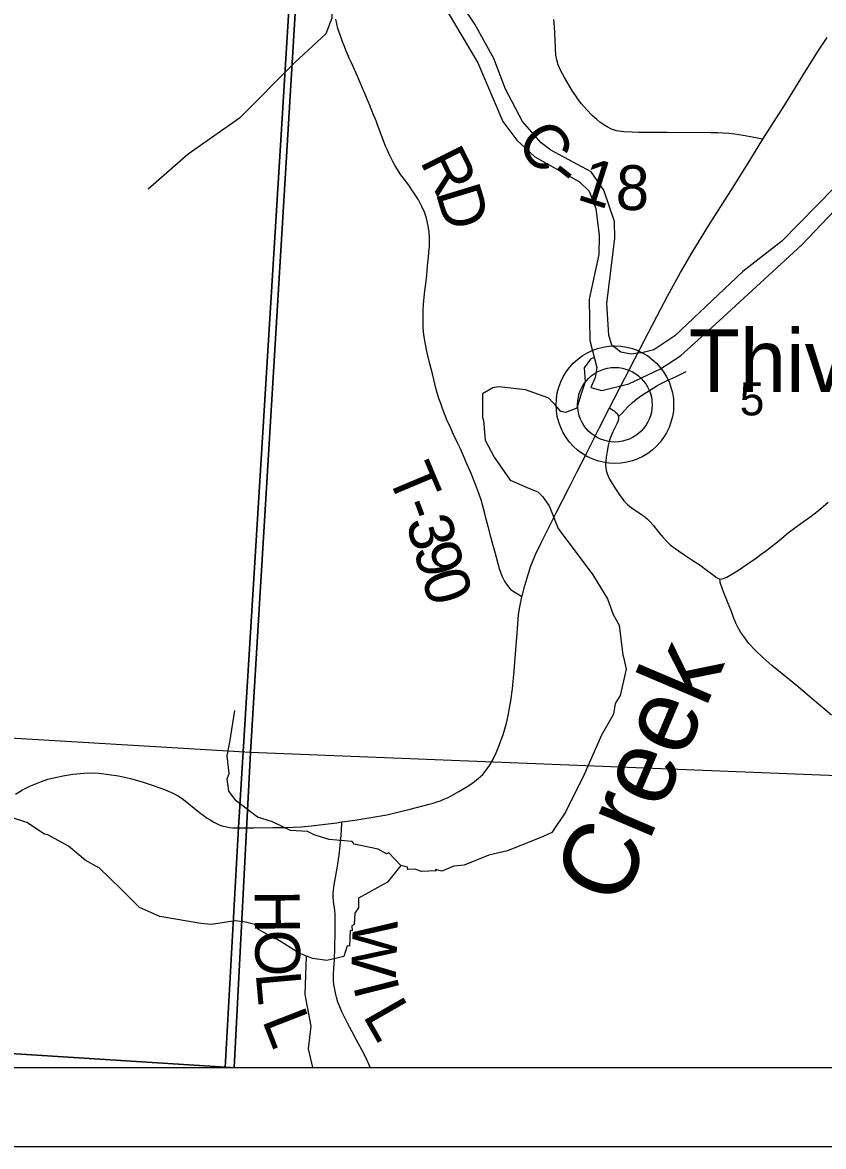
# Model space of a CAD drawing. Extents: x 21.4 to 65.3, y 4 to 26.
# Drawn here: x 24.858 to 25.873, y 17.954 to 19.377 of the extents above; entities that cross this region are included whole.
import ezdxf

# ---------------------------------------------------------------- set-up
doc = ezdxf.new("R2010")
doc.units = 0
for name, color, linetype in [('Default', 7, 'Continuous'), ('GM_X_County_Road', 7, 'Continuous'), ('GM_X_County_Road_Text', 7, 'Continuous'), ('GM_X_Major_River', 7, 'Continuous'), ('GM_X_Minor_River', 7, 'Continuous'), ('GM_X_Minor_River_Text', 7, 'Continuous'), ('GM_X_Section', 7, 'Continuous'), ('GM_X_Section_Text', 7, 'Continuous'), ('GM_X_State_Route', 7, 'Continuous'), ('GM_X_Township_Road', 7, 'Continuous'), ('GM_X_Township_Road_Text', 7, 'Continuous'), ('GM_X_Unincorporated', 7, 'Continuous'), ('GM_X_Unincorporated_Location', 7, 'Continuous'), ('GM_X_Unincorporated_Text', 7, 'Continuous'), ('SH_Cut_Line', 7, 'Continuous'), ('SH_Data', 7, 'Continuous')]:
    doc.layers.add(name, color=color, linetype=linetype)

msp = doc.modelspace()

# ---------------------------------------------------------------- linework, layer by layer
at = {"layer": 'Default'}
for points in [[(23.5473, 20.5568), (23.5473, 18.0542), (25.1151, 18.0542), (25.1319, 18.358), (25.2037, 19.5236), (25.229, 19.8268), (25.2761, 20.4088), (25.2828, 20.4818), (24.9947, 20.491), (24.2595, 20.5181), (23.9671, 20.5321)], [(25.1223, 18.0542), (25.1262, 18.0542), (25.1472, 18.4529), (24.1059, 18.5148), (24.0798, 18.1204)], [(25.1262, 18.0542), (26.1864, 18.0542), (26.1936, 18.1661), (26.208, 18.4108), (25.1472, 18.4529)], [(24.0754, 18.0542), (25.1223, 18.0542), (24.0798, 18.1204)]]:
    msp.add_lwpolyline(points, close=True, dxfattribs=at)
msp.add_lwpolyline([(25.878, 20.4484), (25.869, 20.4484), (25.8552, 20.4488), (25.8459, 20.4493), (25.8391, 20.4499), (25.8341, 20.4506), (25.831, 20.4509), (25.8187, 20.4522), (25.809, 20.4526), (25.8002, 20.4525), (25.7909, 20.4519), (25.2828, 20.4818), (25.2761, 20.4088), (25.229, 19.8268), (25.2037, 19.5236), (25.1319, 18.358), (25.1151, 18.0542), (28.6177, 18.0542)], dxfattribs=at)
at = {"layer": 'GM_X_County_Road'}
for points in [[(25.7959, 19.2292), (25.7932, 19.2298), (25.7802, 19.2325), (25.771, 19.2342), (25.7599, 19.2358), (25.7528, 19.2364), (25.7457, 19.237), (25.7383, 19.2372), (25.7301, 19.2375), (25.7202, 19.2376), (25.6984, 19.2373), (25.6745, 19.2377), (25.6553, 19.2376), (25.6389, 19.2377), (25.6297, 19.2381), (25.6199, 19.2385), (25.6103, 19.2399), (25.6041, 19.2419), (25.5985, 19.2448), (25.5943, 19.2473), (25.5894, 19.251), (25.5856, 19.2542), (25.5794, 19.2597), (25.5727, 19.2666), (25.5661, 19.2743), (25.562, 19.2796), (25.5589, 19.2841), (25.5548, 19.2903), (25.5505, 19.2971), (25.5446, 19.3073), (25.5396, 19.3165), (25.5368, 19.3234), (25.5349, 19.3299), (25.5338, 19.3359), (25.5331, 19.3445), (25.5323, 19.3641), (25.532, 19.3715), (25.5311, 19.3808)], [(25.6018, 18.8892), (25.6058, 18.8865), (25.6076, 18.8853), (25.6092, 18.8839), (25.6107, 18.8824), (25.6119, 18.8807), (25.6124, 18.8795), (25.6128, 18.8781), (25.613, 18.8765), (25.6128, 18.8751), (25.6126, 18.8736), (25.6123, 18.8721), (25.6109, 18.8688), (25.6084, 18.864), (25.6059, 18.8589), (25.6037, 18.8539), (25.6018, 18.8482), (25.6, 18.8414), (25.5986, 18.8342), (25.5973, 18.827), (25.5968, 18.8218), (25.5965, 18.8172), (25.5968, 18.8133), (25.5974, 18.8098), (25.5986, 18.806), (25.6, 18.8026), (25.6017, 18.7991), (25.6049, 18.7935), (25.6091, 18.7866), (25.6143, 18.779), (25.6165, 18.776), (25.618, 18.7741), (25.6198, 18.7717), (25.6227, 18.7685), (25.6244, 18.7668), (25.6272, 18.7644), (25.6307, 18.7618), (25.6327, 18.7604), (25.6434, 18.7533), (25.6459, 18.7515), (25.6478, 18.75), (25.6492, 18.7488), (25.6531, 18.745), (25.6568, 18.7409), (25.664, 18.7316), (25.6695, 18.7249), (25.6741, 18.7199), (25.6785, 18.7157), (25.6846, 18.7112), (25.6957, 18.7035), (25.706, 18.6969), (25.7163, 18.69), (25.7179, 18.6888)], [(25.7414, 18.6725), (25.7438, 18.6726), (25.7461, 18.673), (25.7502, 18.6749), (25.7545, 18.6773), (25.7648, 18.6836), (25.7761, 18.6912), (25.7879, 18.6995), (25.7938, 18.7039), (25.7993, 18.7079), (25.8047, 18.712), (25.8142, 18.7197), (25.8252, 18.7288), (25.8295, 18.7322), (25.8378, 18.7385), (25.8438, 18.7428), (25.8483, 18.746), (25.8524, 18.7488), (25.857, 18.752), (25.8609, 18.755), (25.8661, 18.7594), (25.8783, 18.7698)], [(25.7179, 18.6888), (25.7236, 18.6848), (25.7332, 18.6773), (25.737, 18.6745), (25.7394, 18.6732), (25.7414, 18.6725)], [(25.8827, 18.5), (25.8716, 18.5093), (25.8525, 18.5257), (25.8403, 18.5362), (25.8203, 18.5524), (25.8072, 18.563), (25.7956, 18.5734), (25.7861, 18.5825), (25.7782, 18.591), (25.7728, 18.598), (25.7679, 18.6049), (25.7647, 18.6109), (25.7616, 18.6168), (25.7586, 18.6238), (25.7559, 18.6313), (25.752, 18.6415), (25.7464, 18.6549), (25.7423, 18.6669), (25.7419, 18.6683), (25.7416, 18.6697), (25.7414, 18.6725)], [(25.2986, 18.0542), (25.2969, 18.0585), (25.2927, 18.0675), (25.288, 18.0767), (25.2809, 18.0898), (25.2758, 18.0994), (25.27, 18.1103), (25.263, 18.124), (25.26, 18.1308), (25.2576, 18.1369), (25.2558, 18.1431), (25.2549, 18.1466), (25.2533, 18.1552), (25.2527, 18.1591), (25.2522, 18.1638), (25.252, 18.1683), (25.252, 18.1716), (25.2526, 18.1802), (25.2534, 18.1902), (25.2537, 18.206), (25.2541, 18.2254), (25.2544, 18.2384), (25.2541, 18.2481), (25.2533, 18.2566), (25.2527, 18.2611), (25.2523, 18.2648), (25.2519, 18.2697), (25.2518, 18.2749), (25.252, 18.2788), (25.2529, 18.2856), (25.2547, 18.2949), (25.2574, 18.3092), (25.2594, 18.3228), (25.2606, 18.3348), (25.2618, 18.3485), (25.2627, 18.3627), (25.2628, 18.365)]]:
    msp.add_lwpolyline(points, dxfattribs=at)
at = {"layer": 'GM_X_Major_River'}
for points in [[(25.8861, 19.1677), (25.8199, 19.1002), (25.7702, 19.0619), (25.6844, 18.9806), (25.6577, 18.9626), (25.6441, 18.9591), (25.6289, 18.9572), (25.6161, 18.9597), (25.6047, 18.9684), (25.6008, 18.9813), (25.5983, 19.0215), (25.6085, 19.1042), (25.608, 19.1251), (25.5945, 19.1648), (25.5785, 19.1879), (25.5273, 19.2153), (25.5152, 19.2247), (25.4916, 19.2519), (25.4698, 19.2927), (25.4552, 19.3313), (25.4311, 19.3748), (25.4045, 19.4152), (25.3821, 19.4371), (25.3472, 19.4513)], [(25.3637, 19.4231), (25.3837, 19.4125), (25.4348, 19.3259), (25.4666, 19.2517), (25.4841, 19.2279), (25.5069, 19.2068), (25.5638, 19.1753), (25.576, 19.1636), (25.5844, 19.1416), (25.5884, 19.1075), (25.5882, 19.0832), (25.576, 19.027), (25.5767, 18.9747), (25.5855, 18.9402), (25.5833, 18.9277), (25.5781, 18.9151), (25.5918, 18.9114), (25.6261, 18.9196), (25.6661, 18.9388), (25.6914, 18.9549), (25.7403, 18.9995), (25.8449, 19.0958), (25.9201, 19.1747)]]:
    msp.add_lwpolyline(points, dxfattribs=at)
at = {"layer": 'GM_X_Minor_River'}
for points in [[(25.2529, 19.4818), (25.2455, 19.4726), (25.2407, 19.4376), (25.2493, 19.4043), (25.2502, 19.3826), (25.2423, 19.3625), (25.2031, 19.3266), (25.1333, 19.256), (25.0683, 19.2105), (25.0174, 19.1661)], [(25.582, 18.953), (25.5774, 18.9509), (25.5695, 18.9398), (25.5706, 18.922), (25.5654, 18.9056), (25.5601, 18.8889), (25.5457, 18.8835), (25.54, 18.8847), (25.5351, 18.8904), (25.5249, 18.9014), (25.4954, 18.9119), (25.4614, 18.916), (25.4538, 18.9145), (25.441, 18.9069), (25.441, 18.8772), (25.4421, 18.8734), (25.4441, 18.8483), (25.4554, 18.8267), (25.4759, 18.7975), (25.5034, 18.7857)], [(25.5031, 18.7858), (25.511, 18.7831), (25.5167, 18.777), (25.525, 18.7653), (25.5364, 18.7364), (25.5803, 18.678), (25.5992, 18.6476), (25.6064, 18.6275), (25.614, 18.6142), (25.6186, 18.5762), (25.6193, 18.5735), (25.6228, 18.5584), (25.6149, 18.5253), (25.6088, 18.515), (25.6066, 18.5013), (25.5915, 18.4747), (25.5696, 18.4252), (25.5458, 18.3772), (25.5284, 18.3517), (25.5175, 18.3468), (25.4725, 18.3284), (25.4487, 18.323), (25.4177, 18.3104), (25.4045, 18.3089), (25.3894, 18.3028), (25.3811, 18.305), (25.3822, 18.3031), (25.3814, 18.305), (25.3822, 18.3031), (25.3637, 18.3023), (25.355, 18.3053), (25.3463, 18.3049), (25.3459, 18.3076), (25.3376, 18.3099), (25.3221, 18.3258), (25.3194, 18.3246), (25.3085, 18.3307), (25.2782, 18.3367), (25.2756, 18.3401), (25.2468, 18.3427), (25.2313, 18.3473), (25.2275, 18.3488), (25.2192, 18.3529), (25.1977, 18.3544), (25.175, 18.365), (25.1561, 18.371), (25.1288, 18.3919), (25.1197, 18.404), (25.1175, 18.4196), (25.1201, 18.4264), (25.1174, 18.4489), (25.1208, 18.466), (25.1272, 18.5059)], [(25.0066, 18.2566), (24.983, 18.2805), (24.9558, 18.3067), (24.9376, 18.3165), (24.9168, 18.3344), (24.8903, 18.3487), (24.8862, 18.3495), (24.8639, 18.3643), (24.8196, 18.3786)], [(25.3376, 18.3099), (25.3206, 18.2889), (25.2839, 18.2687), (25.2836, 18.2561), (25.279, 18.2497), (25.2783, 18.2352), (25.2753, 18.2337), (25.2757, 18.2272), (25.2734, 18.2276), (25.2723, 18.2079), (25.2696, 18.2082), (25.2651, 18.1945), (25.2439, 18.1895), (25.2254, 18.1922), (25.2088, 18.199), (25.1804, 18.2168), (25.1781, 18.2171), (25.1573, 18.2289), (25.1524, 18.2353), (25.1407, 18.2383), (25.1275, 18.2398), (25.0972, 18.2352), (25.084, 18.2363), (25.0322, 18.2453), (25.0066, 18.2566)], [(25.2174, 18.1955), (25.216, 18.1467), (25.2234, 18.1066), (25.2199, 18.0778), (25.2254, 18.0542)]]:
    msp.add_lwpolyline(points, dxfattribs=at)
at = {"layer": 'GM_X_Section'}
for points in [[(24.1671, 19.5117), (25.208, 19.459), (25.1472, 18.4529), (24.1059, 18.5148)], [(25.208, 19.459), (26.2708, 19.4063), (26.2556, 19.168), (26.2403, 18.9172), (26.2238, 18.6579), (26.208, 18.4108), (25.1472, 18.4529)]]:
    msp.add_lwpolyline(points, close=True, dxfattribs=at)
at = {"layer": 'GM_X_State_Route'}
for points in [[(25.7959, 19.2292), (25.8234, 19.2728), (25.8507, 19.3169), (25.866, 19.3414), (25.877, 19.358)], [(25.5234, 18.7352), (25.5248, 18.7379), (25.5341, 18.7565), (25.5504, 18.7883), (25.5578, 18.8028), (25.5604, 18.8079), (25.5716, 18.8298), (25.5891, 18.8642), (25.6018, 18.8892), (25.6401, 18.9637), (25.6616, 19.005), (25.6754, 19.0315), (25.6914, 19.0605), (25.7063, 19.0858), (25.7271, 19.1197), (25.758, 19.1688), (25.7804, 19.2045), (25.7959, 19.2292)], [(25.5022, 18.6891), (25.5031, 18.692), (25.5078, 18.7034), (25.5147, 18.7176), (25.5234, 18.7352)], [(25.491, 18.6511), (25.4943, 18.6642), (25.4989, 18.6797), (25.5022, 18.6891)], [(25.1321, 18.3575), (25.1356, 18.3574), (25.1519, 18.3575), (25.1754, 18.3578), (25.1911, 18.3581), (25.2112, 18.3588), (25.2242, 18.3601), (25.2343, 18.3613), (25.2564, 18.3641), (25.2628, 18.365), (25.2792, 18.3673), (25.3019, 18.371), (25.3196, 18.3742), (25.3493, 18.3814), (25.3733, 18.3876), (25.3783, 18.389), (25.3831, 18.3904), (25.3875, 18.3919), (25.3917, 18.3937), (25.3963, 18.3957), (25.4012, 18.3982), (25.4108, 18.4034), (25.4202, 18.409), (25.4285, 18.4146), (25.4355, 18.4201), (25.4411, 18.4253), (25.4455, 18.4304), (25.4498, 18.4366), (25.4538, 18.4436), (25.458, 18.4525), (25.4624, 18.4631), (25.467, 18.4757), (25.4711, 18.4899), (25.4734, 18.4996), (25.4767, 18.5182), (25.4789, 18.5334), (25.4811, 18.5565), (25.4845, 18.6042), (25.4864, 18.6273), (25.4877, 18.6353), (25.4907, 18.6501), (25.491, 18.6511)], [(24.8495, 18.4002), (24.8585, 18.4055), (24.8679, 18.4102), (24.8825, 18.4162), (24.8904, 18.419), (24.8999, 18.4215), (24.912, 18.424), (24.9221, 18.4256), (24.9359, 18.4268), (24.9455, 18.427), (24.9556, 18.4266), (24.9678, 18.4253), (24.9801, 18.4233), (24.9952, 18.42), (25.011, 18.4155), (25.0239, 18.4113), (25.038, 18.4062), (25.0472, 18.4023), (25.0553, 18.3979), (25.0621, 18.3935), (25.0827, 18.3769), (25.087, 18.3735), (25.0924, 18.3698), (25.0961, 18.3675), (25.1006, 18.3648), (25.1056, 18.3623), (25.1108, 18.3603), (25.1172, 18.3587), (25.1209, 18.3581), (25.1249, 18.3577), (25.1321, 18.3575)]]:
    msp.add_lwpolyline(points, dxfattribs=at)
at = {"layer": 'GM_X_Township_Road'}
for points in [[(25.4907, 18.6501), (25.4859, 18.6528), (25.4809, 18.6559), (25.4779, 18.6582), (25.4748, 18.6613), (25.4714, 18.6659), (25.4686, 18.6703), (25.4656, 18.6762), (25.4624, 18.6854), (25.4569, 18.7062), (25.4545, 18.7149), (25.4519, 18.7242), (25.4479, 18.7392), (25.4456, 18.7482), (25.4433, 18.757), (25.4409, 18.7663), (25.439, 18.7728), (25.4358, 18.7822), (25.4319, 18.792), (25.4254, 18.8081), (25.4211, 18.8184), (25.4166, 18.8287), (25.4129, 18.8372), (25.4092, 18.845), (25.4042, 18.8557), (25.4003, 18.8642), (25.3954, 18.875), (25.3923, 18.883), (25.3902, 18.8883), (25.3879, 18.8947), (25.3857, 18.9012), (25.3823, 18.9125), (25.3773, 18.9324), (25.3741, 18.9451), (25.3709, 18.959), (25.3683, 18.9718), (25.3667, 18.9816), (25.3658, 18.9909), (25.3655, 19.0009), (25.3658, 19.0134), (25.3667, 19.0252), (25.3679, 19.0375), (25.3689, 19.0461), (25.3702, 19.0573), (25.3713, 19.0684), (25.3718, 19.0731), (25.3724, 19.0795), (25.3729, 19.0863), (25.3735, 19.0938), (25.3737, 19.1043), (25.3732, 19.1117), (25.3721, 19.1196), (25.3698, 19.1292), (25.3672, 19.1368), (25.364, 19.1442), (25.3597, 19.1524), (25.3548, 19.1603), (25.3505, 19.1665), (25.3474, 19.171), (25.3373, 19.1844), (25.3322, 19.1922), (25.3297, 19.1965), (25.3272, 19.2009), (25.3225, 19.2103), (25.32, 19.2162), (25.3182, 19.2207), (25.31, 19.2422), (25.308, 19.2474), (25.306, 19.2526), (25.3021, 19.2624), (25.2976, 19.2733), (25.2969, 19.275), (25.2918, 19.287), (25.2888, 19.2938), (25.2866, 19.299), (25.2842, 19.3047), (25.282, 19.3098), (25.277, 19.3212), (25.2745, 19.3268), (25.2722, 19.3319), (25.2696, 19.3382), (25.2679, 19.3422), (25.2659, 19.3468), (25.2632, 19.354), (25.2604, 19.3613), (25.2577, 19.3696), (25.2549, 19.3811)], [(25.6128, 18.8781), (25.6166, 18.8817), (25.6254, 18.8909), (25.6306, 18.8959), (25.6362, 18.9006), (25.6423, 18.905), (25.6521, 18.9114), (25.6617, 18.9172), (25.6655, 18.9193), (25.6755, 18.9242), (25.6852, 18.9286), (25.6986, 18.9352)]]:
    msp.add_lwpolyline(points, dxfattribs=at)
at = {"layer": 'GM_X_Unincorporated'}
for radius in [0.0744, 0.0472]:
    msp.add_circle((25.6084, 18.8932), radius, dxfattribs=at)
at = {"layer": 'GM_X_Unincorporated_Location'}
msp.add_line((25.6084, 18.8932), (25.6084, 18.8932), dxfattribs=at)
at = {"layer": 'SH_Cut_Line'}
msp.add_lwpolyline([(23.5473, 24.8542), (23.5473, 18.0542), (28.6177, 18.0542)], dxfattribs=at)
at = {"layer": 'SH_Data'}
for p, q in [((23.5473, 18.0542), (30.3473, 18.0542)), ((23.4473, 17.9542), (30.4473, 17.9542))]:
    msp.add_line(p, q, dxfattribs=at)

# ---------------------------------------------------------------- texts
at = {"layer": 'GM_X_County_Road_Text'}
for s, rotation, p in [('C', 309.0877, (25.4814, 19.2243)), ('-', 322.1398, (25.5209, 19.1782)), ('1', 342.3302, (25.5585, 19.1537)), ('8', 358.4168, (25.609, 19.1402)), ('H', 270.4517, (25.1524, 18.2786)), ('W', 268.0851, (25.2768, 18.2412)), ('O', 270.5895, (25.1528, 18.2284)), ('L', 275.1722, (25.1536, 18.1735)), ('I', 284.1903, (25.2765, 18.1581)), ('L', 299.8274, (25.2885, 18.1198)), ('L', 291.2729, (25.1614, 18.1142))]:
    msp.add_text(s, height=0.0568, rotation=rotation, dxfattribs=at).set_placement(p)
at = {"layer": 'GM_X_Minor_River_Text'}
msp.add_text('Creek', height=0.0947, rotation=66.9988, dxfattribs=at).set_placement((25.6159, 18.2552))
at = {"layer": 'GM_X_Section_Text'}
msp.add_text('5', height=0.0419, rotation=0, dxfattribs=at).set_placement((25.7665, 18.8797))
at = {"layer": 'GM_X_Township_Road_Text'}
for s, rotation, p in [('R', 296.6427, (25.361, 19.2014)), ('D', 286.9367, (25.381, 19.1621)), ('T', 292.754, (25.3197, 18.8047)), ('-', 290.72, (25.336, 18.766)), ('3', 284.9968, (25.3437, 18.7456)), ('9', 285.5967, (25.353, 18.7112)), ('0', 287.344, (25.3629, 18.6756))]:
    msp.add_text(s, height=0.0568, rotation=rotation, dxfattribs=at).set_placement(p)
at = {"layer": 'GM_X_Unincorporated_Text'}
msp.add_text('Thivener', height=0.07898, rotation=0, dxfattribs=at).set_placement((25.702, 18.9095))

doc.saveas('drawing.dxf')
